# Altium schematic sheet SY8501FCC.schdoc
size 127 x 101 mm
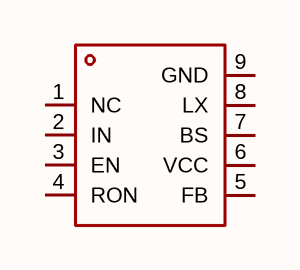
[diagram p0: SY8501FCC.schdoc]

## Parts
U?  sy8501fcc  [SO-8_L4.9-W3.9-P1.27-LS6.0-BL-EP]  (value not drawn)

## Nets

Not connected (* = marked no-connect by the designer): U? 1(NC) 2(IN) 3(EN) 4(RON) 5(FB) 6(VCC) 7(BS) 8(LX) 9(GND)

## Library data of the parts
U? = sy8501fcc: 功能类型:降压型;工作电压:7V~100V;输出电压:-;输出电流:1A;输出类型:可调;; Manufacturer: Silergy(矽力杰); AddInBom: yes; ModelId: 756fba4e187a48c69a2c935cd5c4465b; ModelName: SO-8_L4.9-W3.9-H1.5-LS5.9-P1.27; ModelTransform: 240.39054,192.913,0,270,0,0,0.004,-0.002,0; Function: 降压型; Output Current: 1A; Frequency - Switching: 200kHz~1MHz; Synchronous Rectifier: 是; Number of Outputs: 1; Topology: 降压式; Quiescent Current: 400uA; Switch tube (built-in/external): 内置; Output Type: 可调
